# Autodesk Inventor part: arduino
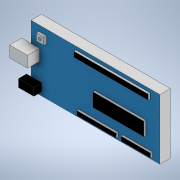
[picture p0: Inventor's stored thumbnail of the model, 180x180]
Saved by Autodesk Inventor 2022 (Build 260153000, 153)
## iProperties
Created: 2021-06
Part Number: arduino
Material: Generic
Document SubType Name: Modeling
Designer: Chimms
Density: 1 g/cm^3
Appearance: Default
Author: Chimms
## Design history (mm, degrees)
sketch "Sketch1"
  geometry: L1 (0, 0)-(64, 0); L2 (64, 0)-(64, 30); L3 (64, 30)-(0, 30); L4 (0, 30)-(0, 0)
  constraints: 8 end point, 2 parallel, 1 horizontal, 1 perpendicular
  dimensions: "d0" = 64 distance of L3.end L2.end; "d1" = 30 distance of L2.end L1.end
extrude "Extrusion1" new body sketch "Sketch1" distance "d2" = 1.2; taper "d3" = 0 deg
sketch "Sketch2"
  geometry: L1 (3.897, 27.093)-(7.564, 27.093); L2 (7.564, 27.093)-(7.564, 23.609); L3 (7.564, 23.609)-(3.897, 23.609); L4 (3.897, 23.609)-(3.897, 27.093); 1 further point
  constraints: 8 end point, 2 parallel, 1 horizontal, 1 perpendicular
extrude "Extrusion2" join sketch "Sketch2" distance "d4" = 1.2; taper "d5" = 0 deg
sketch "Sketch3"
  geometry: C1 r 0.695 at (5.655, 25.449); 1 further point
  constraints: 1 centre point
extrude "Extrusion3" join sketch "Sketch3" distance "d6" = 0.3; taper "d7" = 0 deg
sketch "Sketch4"
  geometry: L1 (4.193, 20.033)-(-4.667, 20.033); L2 (-4.667, 20.033)-(-4.667, 14.437); L3 (-4.667, 14.437)-(4.193, 14.437); L4 (4.193, 14.437)-(4.193, 20.033); 1 further point
  constraints: 8 end point, 2 parallel, 1 horizontal, 1 perpendicular
extrude "Extrusion4" join sketch "Sketch4" distance "d8" = 6; taper "d9" = 0 deg
sketch "Sketch5"
  geometry: L1 (22.269, 28.275)-(59.202, 28.275); L2 (59.202, 28.275)-(59.202, 25.672); L3 (59.202, 25.672)-(22.269, 25.672); L4 (22.269, 25.672)-(22.269, 28.275); 1 further point
  constraints: 8 end point, 2 parallel, 1 horizontal, 1 perpendicular
extrude "Extrusion5" join sketch "Sketch5" distance "d10" = 1; taper "d11" = 0 deg
sketch "Sketch6"
  geometry: L1 (23.671, 3.453)-(43.288, 3.453); L2 (43.288, 3.453)-(43.288, 1.351); L3 (43.288, 1.351)-(23.671, 1.351); L4 (23.671, 1.351)-(23.671, 3.453); L5 (45.69, 3.453)-(60.403, 3.453); L6 (60.403, 3.453)-(60.403, 1.351); L7 (60.403, 1.351)-(45.69, 1.351); L8 (45.69, 1.351)-(45.69, 3.453); 1 further point
  constraints: 16 end point, 4 parallel, 2 horizontal, 2 perpendicular, 2 point on line
extrude "Extrusion6" join sketch "Sketch6" distance "d12" = 1; taper "d13" = 0 deg
sketch "Sketch7"
  geometry: L1 (31.751, 15.539)-(57.078, 15.539); L2 (57.078, 15.539)-(57.078, 8.846); L3 (57.078, 8.846)-(31.751, 8.846); L4 (31.751, 8.846)-(31.751, 15.539); 1 further point
  constraints: 8 end point, 2 parallel, 1 horizontal, 1 perpendicular
extrude "Extrusion7" join sketch "Sketch7" distance "d14" = 1; taper "d15" = 0 deg
sketch "Sketch8"
  geometry: L1 (5.341, 5.761)-(-2.262, 5.761); L2 (-2.262, 5.761)-(-2.262, 1.889); L3 (-2.262, 1.889)-(5.341, 1.889); L4 (5.341, 1.889)-(5.341, 5.761); 1 further point
  constraints: 8 end point, 2 parallel, 1 horizontal, 1 perpendicular
extrude "Extrusion8" join sketch "Sketch8" distance "d16" = 4; taper "d17" = 0 deg
sketch "Sketch9"
  geometry: L1 (0, 0)-(-64, 0) reference; L2 (0, 0)-(-64, 0); L3 (-64, 0)-(-64, 30); L4 (-64, 30)-(0, 30); L5 (0, 30)-(0, 0); 1 further point
  constraints: 8 end point, 2 parallel, 1 horizontal, 1 perpendicular
extrude "Extrusion9" join sketch "Sketch9" distance "d18" = 4; taper "d19" = 0 deg
body "Solid1"
